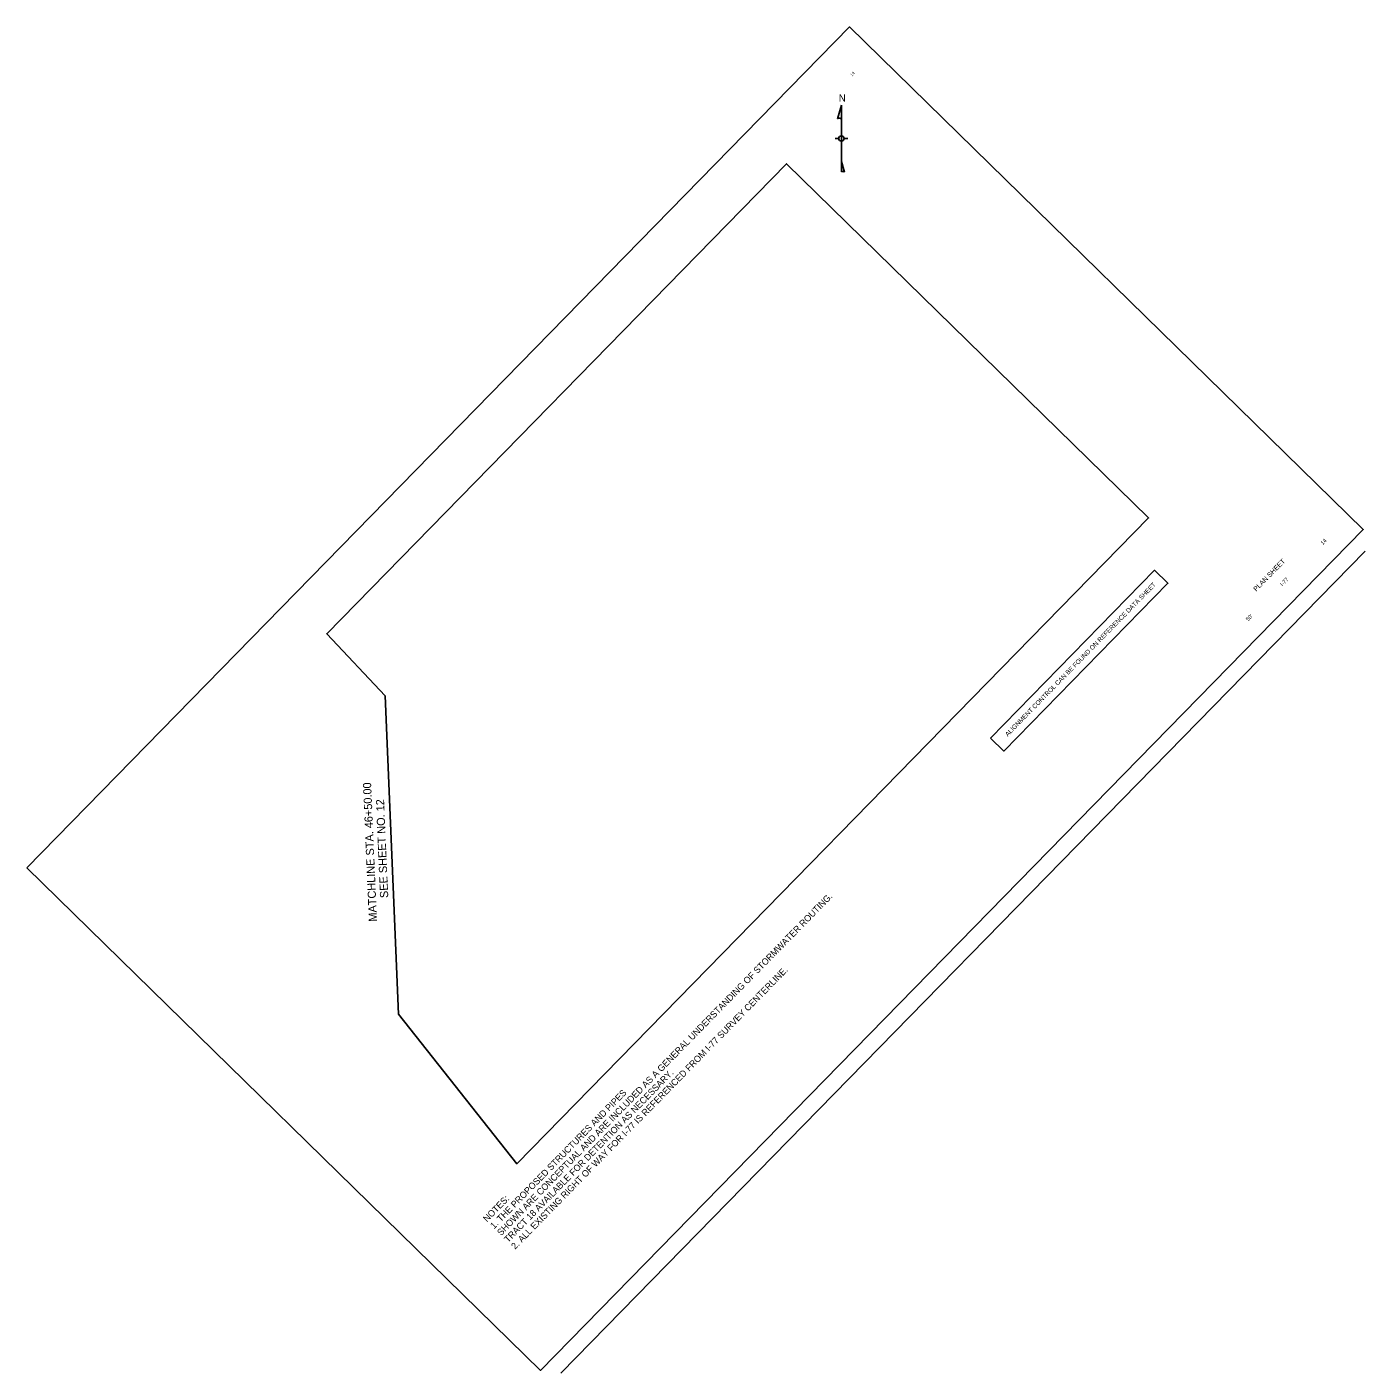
# Model space of a CAD drawing. Extents: x 2006416 to 2008464, y 1136491 to 1138551.
import ezdxf

# ---------------------------------------------------------------- set-up
doc = ezdxf.new("R2010")
doc.units = 0
for name, color, linetype in [('North Arrow', 7, 'Continuous'), ('RD_SHT_IplotShp', 7, 'Continuous'), ('RD_SHT_MatchLine', 7, 'Continuous'), ('RD_SHT_Misc1', 7, 'Continuous'), ('RD_SHT_ShtClip', 7, 'Continuous'), ('RD_SHT_TX', 7, 'Continuous')]:
    doc.layers.add(name, color=color, linetype=linetype)

msp = doc.modelspace()

# ---------------------------------------------------------------- linework, layer by layer
at = {"layer": 'North Arrow'}
for p, q in [((2007657, 1138410.5), (2007662.9, 1138431.6)), ((2007662.9, 1138431.6), (2007662.9, 1138409.4)), ((2007662.9, 1138431.6), (2007662.9, 1138329.3)), ((2007653.2, 1138380.4), (2007658.9, 1138380.4)), ((2007666.9, 1138380.4), (2007672.6, 1138380.4)), ((2007662.9, 1138345.2), (2007662.9, 1138329.3)), ((2007667.4, 1138329.1), (2007662.9, 1138345.2))]:
    msp.add_line(p, q, dxfattribs=at)
msp.add_circle((2007662.9, 1138380.4), 4.02, dxfattribs=at)
for centre, radius, start, end in [((2007659.6, 1138408), 3.59, 22.3707, 136.1387), ((2007665, 1138326.8), 3.3, 43.3397, 130.5607)]:
    msp.add_arc(centre, radius, start, end, dxfattribs=at)
at = {"layer": 'RD_SHT_IplotShp'}
msp.add_lwpolyline([(2006416.4, 1137264.5), (2007675.2, 1138551.1), (2008461.5, 1137781.9), (2007202.6, 1136495.2)], close=True, dxfattribs=at)
at = {"layer": 'RD_SHT_MatchLine'}
msp.add_line((2006985.3, 1137040.4), (2006964.4, 1137527.4), dxfattribs=at)
at = {"layer": 'RD_SHT_ShtClip'}
msp.add_lwpolyline([(2006964.4, 1137527.4), (2006875.3, 1137622.6), (2007578.9, 1138341.7), (2008132.9, 1137799.7), (2007166, 1136811.5), (2006985.3, 1137040.4)], close=True, dxfattribs=at)
at = {"layer": 'RD_SHT_TX'}
msp.add_line((2007233.5, 1136491.1), (2008464.4, 1137749.1), dxfattribs=at)
msp.add_lwpolyline([(2007891.1, 1137462.9), (2008142.3, 1137719.6), (2008162.5, 1137699.8), (2007911.4, 1137443)], close=True, dxfattribs=at)

# ---------------------------------------------------------------- texts
at = {"layer": 'North Arrow'}
msp.add_text('N', height=11.1, rotation=360, dxfattribs=at).set_placement((2007658.8, 1138437))
at = {"layer": 'RD_SHT_MatchLine'}
for s, p in [('MATCHLINE STA. 46+50.00', (2006952.2, 1137182.2)), ('SEE SHEET NO. 12', (2006969.4, 1137218.3))]:
    msp.add_text(s, height=12.5, rotation=92.4547, dxfattribs=at).set_placement(p)
at = {"layer": 'RD_SHT_Misc1'}
for s, p in [('SHOWN ARE CONCEPTUAL AND ARE INCLUDED AS A GENERAL UNDERSTANDING OF STORMWATER ROUTING.  ', (2007142, 1136700.5)), ('2. ALL EXISTING RIGHT OF WAY FOR I-77 IS REFERENCED FROM I-77 SURVEY CENTERLINE.', (2007163.5, 1136679.6)), ('TRACT 18 AVAILABLE FOR DETENTION AS NECESSARY. ', (2007152.8, 1136690.1)), ('1. THE PROPOSED STRUCTURES AND PIPES ', (2007131.3, 1136711)), ('NOTES:', (2007120.6, 1136721.5))]:
    msp.add_text(s, height=10, rotation=45.6253, dxfattribs=at).set_placement(p)
at = {"layer": 'RD_SHT_TX'}
for s, height, p in [('14', 4.5, (2007679.1, 1138475.1)), ('14', 6, (2008399.7, 1137758)), ('PLAN SHEET', 7.5, (2008297.8, 1137686.7)), ('I-77', 6, (2008337.8, 1137694.8)), ('ALIGNMENT CONTROL CAN BE FOUND ON REFERENCE DATA SHEET', 7, (2007917.6, 1137464.7)), ("50'", 6, (2008285.5, 1137641.3))]:
    msp.add_text(s, height=height, rotation=45.6253, dxfattribs=at).set_placement(p)

doc.saveas('drawing.dxf')
